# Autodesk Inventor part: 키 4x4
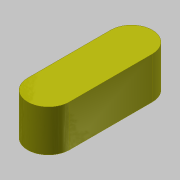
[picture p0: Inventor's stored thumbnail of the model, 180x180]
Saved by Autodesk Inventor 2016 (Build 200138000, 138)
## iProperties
Created: 2015-12
Part Number: 키 4x4
Document SubType Name: Modeling
Designer: mdu
Density: 7.86 g/cm^3
Material: 강철, 연강
Appearance: 노란색
Mass: 1.40117 g
Surface Area: 2.03398 cm^2
Volume: 0.178265 cm^3
Author: mdu
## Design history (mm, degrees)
sketch "스케치1"
  geometry: L1 (-2, -10)-(-2, -2) reference; L2 (2, -2)-(2, -10) reference; A1 r 2 centre (0, -2) between (2, -2) and (-2, -2) reference; A2 r 2 centre (0, -10) between (-2, -10) and (2, -10) reference; 1 further point
extrude "돌출1" new body sketch "스케치1" distance "d0" = 4; taper "d1" = 0 deg
node "솔리드1"
node "참조1"
